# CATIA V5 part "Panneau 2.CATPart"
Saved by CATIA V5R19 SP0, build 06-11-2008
Part number: Panneau 2
Bounding box of the stored display mesh (mm): x -141.216 to 58.784, y -100 to 100, z 0 to 5
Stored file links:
  G:\EU_thinkMotion\CFAO_2010\St2M_groupe2\St2M_groupe2\csayed\csayed\csayed\Panneau 2.CATPart
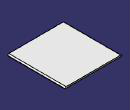
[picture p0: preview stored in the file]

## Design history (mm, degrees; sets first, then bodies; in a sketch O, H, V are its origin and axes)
Body1 (main body)
  Sketch1 on zx-plane, origin (0, 0, 0), H (-1, 0, 0), V (0, 0, 1)
    line L1 (-58.7845, 0) -> (141.2155, 0)
    point P1 (-58.7845, 0)
    line L2 (-58.7845, 5) -> (135.5483, 5)
    line L3 (135.5483, 5) -> (141.2155, 0)
    line L4 (-58.7845, 5) -> (-58.7845, 0)
    distance L2 L1 = 5
    coincidence: P1 H
    horizontal: L1 H, L2 H
    vertical: L4 V
  Pad1: profile Sketch1, direction (0, 1, 0), length 100, mirrored extent
  Fillet1: radius 4, on edge [face of Pad1 from Sketch1.L4 | face of Pad1 from Sketch1.L2]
